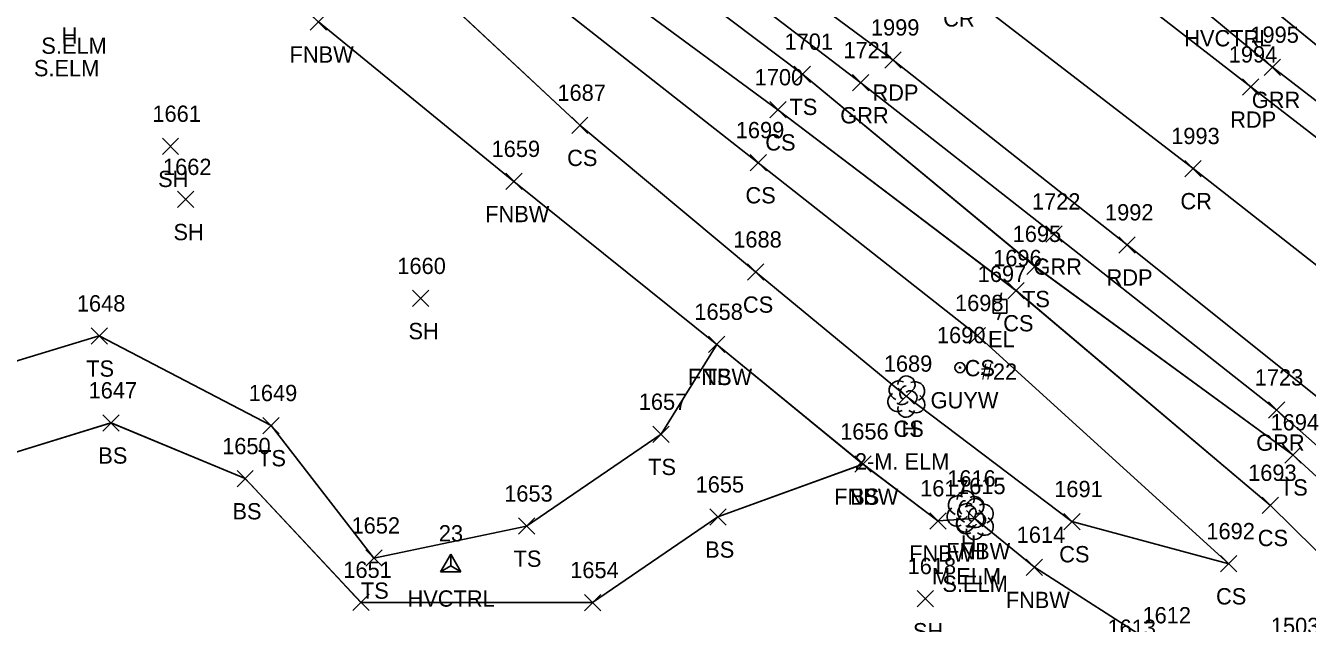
# Model space of a CAD drawing. Extents: x 1415642 to 1422021, y 544543 to 547232.
# Drawn here: x 1415966.4 to 1416123.6, y 546804.9 to 546878.2 of the extents above; entities that cross this region are included whole.
import ezdxf

# ---------------------------------------------------------------- set-up
doc = ezdxf.new("R2010")
doc.units = 0
for name, color, linetype in [('C_A', 7, 'Continuous'), ('C_I', 7, 'Continuous'), ('CPSM', 7, 'Continuous'), ('L_A', 7, 'Continuous'), ('L_C', 7, 'Continuous'), ('L_I', 7, 'Continuous'), ('L_TIC', 7, 'Continuous'), ('LELB', 7, 'Continuous'), ('LFNC', 7, 'Continuous'), ('LTD', 7, 'Continuous'), ('P_A', 7, 'Continuous'), ('P_I', 7, 'Continuous'), ('P_TIC', 7, 'Continuous'), ('PET', 7, 'Continuous'), ('PRC', 7, 'Continuous'), ('R_A', 7, 'Continuous'), ('R_I', 7, 'Continuous'), ('R_TIC', 7, 'Continuous'), ('RGR', 7, 'Continuous'), ('U_A', 7, 'Continuous'), ('U_C', 7, 'Continuous'), ('U_I', 7, 'Continuous'), ('UEPT', 7, 'Continuous'), ('UPGW', 7, 'Continuous')]:
    doc.layers.add(name, color=color, linetype=linetype)

msp = doc.modelspace()

# ---------------------------------------------------------------- linework, layer by layer
at = {"layer": 'CPSM'}
for p, q in [((1416017.27, 546811.23), (1416018.52, 546813.39)), ((1416019.77, 546811.23), (1416018.52, 546813.39)), ((1416018.52, 546811.95), (1416018.52, 546813.39)), ((1416017.27, 546811.23), (1416018.52, 546811.95)), ((1416017.27, 546811.23), (1416019.77, 546811.23)), ((1416018.52, 546811.95), (1416018.52, 546811.95)), ((1416018.52, 546811.95), (1416019.77, 546811.23))]:
    msp.add_line(p, q, dxfattribs=at)
at = {"layer": 'L_TIC'}
for points in [[(1416001.28, 546877.71), (1416003.28, 546879.71)], [(1416003.28, 546877.71), (1416001.28, 546879.71)], [(1416060.67, 546871.28), (1416062.67, 546873.28)], [(1416062.67, 546871.28), (1416060.67, 546873.28)], [(1416057.66, 546866.92), (1416059.66, 546868.92)], [(1416059.66, 546866.92), (1416057.66, 546868.92)], [(1416033.36, 546865.02), (1416035.36, 546867.02)], [(1416035.36, 546865.02), (1416033.36, 546867.02)], [(1415983.14, 546862.44), (1415985.14, 546864.44)], [(1415985.14, 546862.44), (1415983.14, 546864.44)], [(1416055.24, 546860.43), (1416057.24, 546862.43)], [(1416057.24, 546860.43), (1416055.24, 546862.43)], [(1416025.27, 546858.13), (1416027.27, 546860.13)], [(1416027.27, 546858.13), (1416025.27, 546860.13)], [(1415985.01, 546855.92), (1415987.01, 546857.92)], [(1415987.01, 546855.92), (1415985.01, 546857.92)], [(1416054.92, 546847.02), (1416056.92, 546849.02)], [(1416056.92, 546847.02), (1416054.92, 546849.02)], [(1416089.2, 546847.7), (1416091.2, 546849.7)], [(1416091.2, 546847.7), (1416089.2, 546849.7)], [(1416086.86, 546844.73), (1416088.86, 546846.73)], [(1416088.86, 546844.73), (1416086.86, 546846.73)], [(1416013.84, 546843.77), (1416015.84, 546845.77)], [(1416015.84, 546843.77), (1416013.84, 546845.77)], [(1415974.39, 546839.17), (1415976.39, 546841.17)], [(1415976.39, 546839.17), (1415974.39, 546841.17)], [(1416082.13, 546839.22), (1416084.13, 546841.22)], [(1416084.13, 546839.22), (1416082.13, 546841.22)], [(1416050.15, 546838.14), (1416052.15, 546840.14)], [(1416052.15, 546838.14), (1416050.15, 546840.14)], [(1416050.15, 546838.14), (1416052.15, 546840.14)], [(1416052.15, 546838.14), (1416050.15, 546840.14)], [(1416073.4, 546831.78), (1416075.4, 546833.78)], [(1416075.4, 546831.78), (1416073.4, 546833.78)], [(1415975.83, 546828.5), (1415977.83, 546830.5)], [(1415977.83, 546828.5), (1415975.83, 546830.5)], [(1415995.48, 546828.17), (1415997.48, 546830.17)], [(1415997.48, 546828.17), (1415995.48, 546830.17)], [(1416043.33, 546827.1), (1416045.33, 546829.1)], [(1416045.33, 546827.1), (1416043.33, 546829.1)], [(1416120.84, 546824.58), (1416122.84, 546826.58)], [(1416122.84, 546824.58), (1416120.84, 546826.58)], [(1416068.09, 546823.45), (1416070.09, 546825.45)], [(1416070.09, 546823.45), (1416068.09, 546825.45)], [(1416068.09, 546823.45), (1416070.09, 546825.45)], [(1416070.09, 546823.45), (1416068.09, 546825.45)], [(1415992.3, 546821.66), (1415994.3, 546823.66)], [(1415994.3, 546821.66), (1415992.3, 546823.66)], [(1416118.09, 546818.38), (1416120.09, 546820.38)], [(1416120.09, 546818.38), (1416118.09, 546820.38)], [(1416050.3, 546816.96), (1416052.3, 546818.96)], [(1416052.3, 546816.96), (1416050.3, 546818.96)], [(1416077.29, 546816.48), (1416079.29, 546818.48)], [(1416079.29, 546816.48), (1416077.29, 546818.48)], [(1416081.81, 546816.76), (1416083.81, 546818.76)], [(1416083.81, 546816.76), (1416081.81, 546818.76)], [(1416093.73, 546816.39), (1416095.73, 546818.39)], [(1416095.73, 546816.39), (1416093.73, 546818.39)], [(1416026.82, 546815.84), (1416028.82, 546817.84)], [(1416028.82, 546815.84), (1416026.82, 546817.84)], [(1416008.09, 546811.92), (1416010.09, 546813.92)], [(1416010.09, 546811.92), (1416008.09, 546813.92)], [(1416089.13, 546810.78), (1416091.13, 546812.78)], [(1416091.13, 546810.78), (1416089.13, 546812.78)], [(1416112.97, 546811.22), (1416114.97, 546813.22)], [(1416114.97, 546811.22), (1416112.97, 546813.22)], [(1416075.74, 546806.94), (1416077.74, 546808.94)], [(1416077.74, 546806.94), (1416075.74, 546808.94)], [(1416006.51, 546806.48), (1416008.51, 546808.48)], [(1416008.51, 546806.48), (1416006.51, 546808.48)], [(1416034.92, 546806.45), (1416036.92, 546808.45)], [(1416036.92, 546806.45), (1416034.92, 546808.45)]]:
    msp.add_lwpolyline(points, dxfattribs=at)
at = {"layer": 'LELB'}
for points in [[(1416210.45, 546810.14), (1416187.24, 546828.5), (1416172.35, 546839.03), (1416162.91, 546845.64), (1416145.69, 546861.76), (1416125.16, 546875.54), (1416093.4, 546901.43), (1416075.19, 546919.9), (1416045.66, 546942.32), (1416039.77, 546946.29), (1416015.88, 546971.97), (1415979.91, 546993.7), (1415946.5, 547018.2), (1415914.22, 547042.27), (1415877.25, 547066.68), (1415845.5, 547087.74)], [(1416210.45, 546810.14), (1416187.24, 546828.5), (1416172.36, 546839.03), (1416162.91, 546845.64), (1416145.7, 546861.76), (1416125.16, 546875.54), (1416093.4, 546901.44), (1416075.18, 546919.9), (1416045.66, 546942.32), (1416039.77, 546946.29), (1416015.88, 546971.97), (1415979.91, 546993.7), (1415946.51, 547018.2), (1415914.22, 547042.27), (1415877.24, 547066.68), (1415845.5, 547087.74)], [(1416200.69, 546756.25), (1416177.76, 546767.63), (1416166.72, 546775.57), (1416158.94, 546780.74), (1416149.8, 546790.95), (1416145.27, 546792.19), (1416135.47, 546803.24), (1416119.09, 546819.38), (1416087.86, 546845.73), (1416058.66, 546867.92), (1416017.63, 546898.15), (1415975.94, 546926.54), (1415961.59, 546937.35), (1415930.25, 546967.22), (1415904.85, 546987.6), (1415883.27, 547005.7), (1415850.56, 547030.99), (1415821.69, 547055.02)], [(1416200.69, 546756.25), (1416177.77, 546767.63), (1416166.72, 546775.57), (1416158.93, 546780.74), (1416149.8, 546790.95), (1416145.28, 546792.19), (1416135.47, 546803.24), (1416119.09, 546819.38), (1416087.87, 546845.73), (1416058.67, 546867.92), (1416017.63, 546898.16), (1415975.95, 546926.55), (1415961.6, 546937.34), (1415930.25, 546967.22), (1415904.86, 546987.6), (1415883.28, 547005.7), (1415850.57, 547030.99), (1415821.7, 547055.02)], [(1415881.61, 546996.31), (1415913.06, 546969.47), (1415944.07, 546943.36), (1415978.11, 546916.22), (1416009.92, 546888.85), (1416034.36, 546866.02), (1416055.92, 546848.02), (1416074.4, 546832.78), (1416094.73, 546817.39), (1416113.97, 546812.22), (1416083.13, 546840.22), (1416056.24, 546861.43), (1416014.25, 546894.44), (1415975.94, 546926.54)], [(1415881.62, 546996.31), (1415913.07, 546969.47), (1415944.08, 546943.36), (1415978.12, 546916.23), (1416009.93, 546888.84), (1416034.36, 546866.03), (1416055.93, 546848.02), (1416074.4, 546832.78), (1416094.74, 546817.39), (1416113.98, 546812.22), (1416083.14, 546840.22), (1416056.24, 546861.43), (1416014.25, 546894.43), (1415975.95, 546926.55)], [(1416413.88, 546519.84), (1416385.73, 546558.12), (1416356.85, 546595.36), (1416336.82, 546621.39), (1416300.66, 546661.66), (1416278.22, 546684.25), (1416249.88, 546714.04), (1416230.93, 546728.9), (1416221.86, 546737.5), (1416200.69, 546756.25), (1416176.24, 546778.44), (1416157.26, 546793.38), (1416140.02, 546808.9), (1416121.84, 546825.58), (1416090.2, 546848.7), (1416061.67, 546872.28), (1416021.03, 546902.96), (1415979.27, 546932.57), (1415964.6, 546940.59)], [(1416413.88, 546519.84), (1416385.73, 546558.12), (1416356.85, 546595.36), (1416336.82, 546621.39), (1416300.66, 546661.66), (1416278.22, 546684.25), (1416249.88, 546714.04), (1416230.93, 546728.9), (1416221.87, 546737.51), (1416200.69, 546756.25), (1416176.24, 546778.44), (1416157.26, 546793.38), (1416140.03, 546808.9), (1416121.84, 546825.58), (1416090.21, 546848.7), (1416061.68, 546872.28), (1416021.04, 546902.96), (1415979.28, 546932.57), (1415964.61, 546940.59)], [(1415936.18, 546816.47), (1415954.66, 546833.88), (1415975.39, 546840.17), (1415996.48, 546829.17), (1416009.09, 546812.92), (1416027.82, 546816.84), (1416044.33, 546828.1), (1416051.15, 546839.14)], [(1415936.19, 546816.47), (1415954.66, 546833.88), (1415975.4, 546840.17), (1415996.49, 546829.17), (1416009.1, 546812.92), (1416027.83, 546816.84), (1416044.34, 546828.1), (1416051.16, 546839.14)], [(1415944.33, 546804.96), (1415961.56, 546824.81), (1415976.83, 546829.5), (1415993.3, 546822.66), (1416007.51, 546807.48), (1416035.92, 546807.45), (1416051.3, 546817.96), (1416069.09, 546824.45)], [(1415944.33, 546804.96), (1415961.57, 546824.81), (1415976.84, 546829.5), (1415993.31, 546822.66), (1416007.52, 546807.48), (1416035.92, 546807.45), (1416051.3, 546817.96), (1416069.1, 546824.45)]]:
    msp.add_lwpolyline(points, dxfattribs=at)
at = {"layer": 'LFNC'}
for points in [[(1416115.75, 546796.75), (1416105.56, 546801.9), (1416090.13, 546811.78), (1416082.81, 546817.76), (1416078.29, 546817.48), (1416069.09, 546824.45), (1416051.15, 546839.14), (1416026.27, 546859.13), (1416002.28, 546878.71), (1415967.43, 546909.62), (1415937.82, 546934.52), (1415909.35, 546961.09), (1415874.55, 546995.04)], [(1416115.75, 546796.75), (1416105.57, 546801.9), (1416090.14, 546811.78), (1416082.82, 546817.76), (1416078.29, 546817.48), (1416069.1, 546824.45), (1416051.16, 546839.14), (1416026.28, 546859.13), (1416002.28, 546878.71), (1415967.43, 546909.62), (1415937.83, 546934.51), (1415909.36, 546961.09), (1415874.56, 546995.04)]]:
    msp.add_lwpolyline(points, dxfattribs=at)
at = {"layer": 'LTD'}
for p, q in [((1416074.4, 546832.78), (1416074.4, 546832.78)), ((1416074.4, 546832.78), (1416074.4, 546832.78)), ((1416081.65, 546818.69), (1416081.65, 546818.69)), ((1416081.65, 546818.69), (1416081.65, 546818.69)), ((1416082.81, 546817.76), (1416082.81, 546817.76)), ((1416082.81, 546817.76), (1416082.81, 546817.76))]:
    msp.add_line(p, q, dxfattribs=at)
for centre in [(1416074.44, 546834.21), (1416081.7, 546820.13), (1416082.86, 546819.19)]:
    msp.add_arc(centre, 1.05, 335.5272, 180.9563, dxfattribs=at)
for centre, major_axis, ratio, start_param, end_param in [((1416073.6, 546833.45), (1.21, -0.51), 0.895232, 1.570796, 4.712389), ((1416074.19, 546833.24), (-0.208, -0.792), 0.645439, 3.141593, 6.283185), ((1416075.44, 546833.36), (-1.14, -0.48), 0.949671, 1.570796, 4.712389), ((1416073.31, 546832.07), (0.58, -1.04), 0.959034, 3.141593, 6.283185), ((1416074.9, 546832.61), (-0.5, 0.667), 0.989748, 3.141593, 6.283185), ((1416075.4, 546831.95), (-1.09, 0.79), 0.841452, 1.570796, 4.712389), ((1416074.4, 546831.28), (0.26, 1.06), 0.942809, 1.570796, 4.712389), ((1416073.94, 546832.03), (-0.625, -0.083), 0.423636, 0, 3.141593), ((1416080.86, 546819.36), (1.21, -0.51), 0.895232, 1.570796, 4.712389), ((1416081.45, 546819.15), (-0.208, -0.792), 0.645439, 3.141593, 6.283185), ((1416082.7, 546819.28), (-1.14, -0.48), 0.949671, 1.570796, 4.712389), ((1416080.57, 546817.99), (0.58, -1.04), 0.959034, 3.141593, 6.283185), ((1416082.02, 546818.42), (1.21, -0.51), 0.895232, 1.570796, 4.712389), ((1416082.15, 546818.53), (-0.5, 0.667), 0.989748, 3.141593, 6.283185), ((1416082.6, 546818.22), (-0.208, -0.792), 0.645439, 3.141593, 6.283185), ((1416082.66, 546817.86), (-1.09, 0.79), 0.841452, 1.570796, 4.712389), ((1416083.31, 546817.59), (-0.5, 0.667), 0.989748, 3.141593, 6.283185), ((1416083.85, 546818.34), (-1.14, -0.48), 0.949671, 1.570796, 4.712389), ((1416081.73, 546817.05), (0.58, -1.04), 0.959034, 3.141593, 6.283185), ((1416081.66, 546817.19), (0.26, 1.06), 0.942809, 1.570796, 4.712389), ((1416081.2, 546817.94), (-0.625, -0.083), 0.423636, 0, 3.141593), ((1416082.35, 546817.01), (-0.625, -0.083), 0.423636, 0, 3.141593), ((1416083.81, 546816.92), (-1.09, 0.79), 0.841452, 1.570796, 4.712389), ((1416082.81, 546816.26), (0.26, 1.06), 0.942809, 1.570796, 4.712389)]:
    msp.add_ellipse(centre, major_axis=major_axis, ratio=ratio, start_param=start_param, end_param=end_param, dxfattribs=at)
at = {"layer": 'P_TIC'}
for points in [[(1416071.78, 546873.03), (1416073.78, 546875.03)], [(1416073.78, 546873.03), (1416071.78, 546875.03)], [(1416115.66, 546869.72), (1416117.66, 546871.72)], [(1416117.66, 546869.72), (1416115.66, 546871.72)], [(1416108.6, 546859.71), (1416110.6, 546861.71)], [(1416110.6, 546859.71), (1416108.6, 546861.71)], [(1416100.49, 546850.34), (1416102.49, 546852.34)], [(1416102.49, 546850.34), (1416100.49, 546852.34)]]:
    msp.add_lwpolyline(points, dxfattribs=at)
at = {"layer": 'PET'}
for points in [[(1416435.56, 546537.44), (1416408.53, 546574.61), (1416379.54, 546611.97), (1416358.62, 546637.86), (1416320.38, 546681.18), (1416299.04, 546704.62), (1416270.68, 546734.26), (1416256.1, 546749.21), (1416221.42, 546781.44), (1416197.8, 546803.68), (1416167.45, 546829.93), (1416146.9, 546847.39), (1416116.66, 546870.72), (1416088.42, 546892.72), (1416062.97, 546911.59), (1416031.6, 546935.61), (1415998.08, 546959.73), (1415969.06, 546981.93), (1415936.64, 547006.92)], [(1416435.56, 546537.44), (1416408.53, 546574.62), (1416379.54, 546611.97), (1416358.63, 546637.85), (1416320.38, 546681.18), (1416299.04, 546704.62), (1416270.69, 546734.26), (1416256.1, 546749.21), (1416221.42, 546781.44), (1416197.8, 546803.68), (1416167.45, 546829.93), (1416146.9, 546847.38), (1416116.66, 546870.72), (1416088.42, 546892.72), (1416062.98, 546911.58), (1416031.6, 546935.61), (1415998.08, 546959.73), (1415969.07, 546981.93), (1415936.65, 547006.92)], [(1416417.68, 546520.98), (1416388.9, 546560.28), (1416359.4, 546597.75), (1416339.06, 546622.92), (1416303.08, 546664.45), (1416282.37, 546687.64), (1416253.58, 546717.16), (1416237.44, 546733.28), (1416206.51, 546762.17), (1416181.86, 546784.67), (1416151.94, 546810.47), (1416130.39, 546828.26), (1416101.49, 546851.34), (1416072.78, 546874.03), (1416047.41, 546892.82), (1416017.81, 546915.59), (1415982.21, 546942.39), (1415954.4, 546964.56)], [(1416417.68, 546520.98), (1416388.9, 546560.28), (1416359.4, 546597.76), (1416339.06, 546622.93), (1416303.08, 546664.45), (1416282.37, 546687.65), (1416253.58, 546717.16), (1416237.44, 546733.28), (1416206.51, 546762.17), (1416181.87, 546784.67), (1416151.94, 546810.47), (1416130.39, 546828.26), (1416101.49, 546851.34), (1416072.78, 546874.03), (1416047.41, 546892.82), (1416017.81, 546915.59), (1415982.21, 546942.39), (1415954.4, 546964.56)]]:
    msp.add_lwpolyline(points, dxfattribs=at)
at = {"layer": 'PRC'}
for points in [[(1416425.29, 546532.23), (1416399.16, 546568.17), (1416370.34, 546605), (1416349.98, 546630.03), (1416312.55, 546673.44), (1416291.21, 546696.63), (1416262.58, 546725.99), (1416246.66, 546742.06), (1416214.68, 546772.43), (1416190.4, 546794.67), (1416160.38, 546819.82), (1416139.01, 546837.64), (1416109.6, 546860.71), (1416080.51, 546883.13), (1416051.44, 546902.01), (1416024.84, 546926.07), (1415989.92, 546951.67), (1415962.46, 546973.18)], [(1416425.29, 546532.24), (1416399.16, 546568.17), (1416370.35, 546605), (1416349.98, 546630.03), (1416312.55, 546673.45), (1416291.21, 546696.63), (1416262.58, 546725.99), (1416246.66, 546742.06), (1416214.67, 546772.43), (1416190.4, 546794.67), (1416160.38, 546819.82), (1416139.01, 546837.64), (1416109.6, 546860.71), (1416080.51, 546883.13), (1416051.45, 546902.01), (1416024.84, 546926.07), (1415989.92, 546951.68), (1415962.46, 546973.18)]]:
    msp.add_lwpolyline(points, dxfattribs=at)
at = {"layer": 'R_TIC'}
for points in [[(1416118.32, 546872.14), (1416120.32, 546874.14)], [(1416120.32, 546872.14), (1416118.32, 546874.14)], [(1416067.82, 546870.25), (1416069.82, 546872.25)], [(1416069.82, 546870.25), (1416067.82, 546872.25)], [(1416091.52, 546851.68), (1416093.52, 546853.68)], [(1416093.52, 546851.68), (1416091.52, 546853.68)], [(1416118.85, 546830.08), (1416120.85, 546832.08)], [(1416120.85, 546830.08), (1416118.85, 546832.08)]]:
    msp.add_lwpolyline(points, dxfattribs=at)
at = {"layer": 'RGR'}
for points in [[(1415969.74, 546941.99), (1415991.65, 546929.21), (1416016.29, 546910.93), (1416041.47, 546892.17), (1416068.82, 546871.25), (1416092.52, 546852.68), (1416119.85, 546831.08), (1416143.05, 546810.55), (1416160.13, 546797.47)], [(1415969.75, 546941.99), (1415991.65, 546929.21), (1416016.3, 546910.93), (1416041.48, 546892.18), (1416068.83, 546871.25), (1416092.52, 546852.68), (1416119.86, 546831.08), (1416143.05, 546810.55), (1416160.13, 546797.47)], [(1416226.79, 546787.66), (1416201.13, 546806.07), (1416168.8, 546834.69), (1416149.29, 546850.1), (1416119.32, 546873.14), (1416091.47, 546896.23), (1416072.68, 546914.46)], [(1416226.79, 546787.66), (1416201.13, 546806.07), (1416168.81, 546834.68), (1416149.29, 546850.1), (1416119.32, 546873.14), (1416091.47, 546896.23), (1416072.68, 546914.46)]]:
    msp.add_lwpolyline(points, dxfattribs=at)
at = {"layer": 'UEPT'}
for p, q in [((1416086.08, 546845.46), (1416085.91, 546844.63)), ((1416085.08, 546842.96), (1416085.08, 546844.63)), ((1416085.08, 546844.63), (1416086.74, 546844.63)), ((1416085.91, 546843.79), (1416085.91, 546843.79)), ((1416086.74, 546844.63), (1416086.74, 546842.96)), ((1416086.74, 546842.96), (1416085.08, 546842.96)), ((1416085.66, 546842.13), (1416085.91, 546842.96))]:
    msp.add_line(p, q, dxfattribs=at)
at = {"layer": 'UPGW'}
for radius in [0.625, 0.0833]:
    msp.add_circle((1416081, 546836.28), radius, dxfattribs=at)

# ---------------------------------------------------------------- texts
at = {"layer": 'C_A'}
for p in [(1416108.51, 546875.7), (1416013.22, 546806.95)]:
    msp.add_text('HVCTRL', height=2, dxfattribs=at).set_placement(p)
at = {"layer": 'C_I'}
msp.add_text('23', height=2, dxfattribs=at).set_placement((1416017.06, 546814.95))
at = {"layer": 'L_A'}
for s, p in [('H', (1415970.78, 546876.03)), ('FNBW', (1415998.75, 546873.71)), ('TS', (1416060.08, 546867.28)), ('CS', (1416057.11, 546862.92)), ('CS', (1416032.8, 546861.02)), ('SH', (1415982.62, 546858.44)), ('CS', (1416054.68, 546856.43)), ('FNBW', (1416022.75, 546854.13)), ('SH', (1415984.5, 546851.92)), ('TS', (1416088.61, 546843.7)), ('CS', (1416054.37, 546843.02)), ('CS', (1416086.3, 546840.73)), ('SH', (1416013.33, 546839.77)), ('CS', (1416081.57, 546835.22)), ('TS', (1415973.8, 546835.17)), ('FNBW', (1416047.62, 546834.14)), ('TS', (1416049.56, 546834.14)), ('CS', (1416072.84, 546827.78)), ('H', (1416073.83, 546827.78)), ('BS', (1415975.28, 546824.5)), ('TS', (1415994.89, 546824.17)), ('TS', (1416042.74, 546823.1)), ('BS', (1416067.53, 546819.45)), ('TS', (1416120.25, 546820.58)), ('FNBW', (1416065.57, 546819.45)), ('BS', (1415991.74, 546817.66)), ('H', (1416081.09, 546813.69)), ('CS', (1416117.53, 546814.38)), ('TS', (1416026.23, 546811.84)), ('BS', (1416049.74, 546812.96)), ('FNBW', (1416074.76, 546812.48)), ('FNBW', (1416079.29, 546812.76)), ('H', (1416082.25, 546812.76)), ('CS', (1416093.17, 546812.39)), ('TS', (1416007.5, 546807.92)), ('CS', (1416112.41, 546807.22)), ('FNBW', (1416086.61, 546806.78)), ('SH', (1416075.23, 546802.94))]:
    msp.add_text(s, height=2, dxfattribs=at).set_placement(p)
at = {"layer": 'L_C'}
for s, p in [('S.ELM', (1415968.29, 546874.79)), ('S.ELM', (1415967.38, 546872.03)), ('2-M. ELM', (1416068.1, 546823.78)), ('M.ELM', (1416077.56, 546809.69)), ('S.ELM', (1416078.84, 546808.76))]:
    msp.add_text(s, height=2, dxfattribs=at).set_placement(p)
at = {"layer": 'L_I'}
for s, p in [('1701', (1416059.47, 546875.28)), ('1700', (1416055.81, 546870.92)), ('1687', (1416031.61, 546869.02)), ('1661', (1415981.92, 546866.44)), ('1699', (1416053.49, 546864.43)), ('1659', (1416023.53, 546862.13)), ('1662', (1415983.22, 546859.92)), ('1688', (1416053.18, 546851.02)), ('1695', (1416087.46, 546851.7)), ('1660', (1416011.97, 546847.77)), ('1696', (1416085.07, 546848.73)), ('1648', (1415972.65, 546843.17)), ('1698', (1416080.39, 546843.22)), ('1658', (1416048.41, 546842.14)), ('1658', (1416048.41, 546842.14)), ('1689', (1416071.65, 546835.78)), ('1689', (1416071.65, 546835.78)), ('1647', (1415974.09, 546832.5)), ('1649', (1415993.74, 546832.17)), ('1657', (1416041.59, 546831.1)), ('1656', (1416066.3, 546827.45)), ('1656', (1416066.3, 546827.45)), ('1694', (1416119.1, 546828.58)), ('1650', (1415990.48, 546825.66)), ('1616', (1416079.43, 546821.69)), ('1693', (1416116.35, 546822.38)), ('1653', (1416025.08, 546819.84)), ('1655', (1416048.56, 546820.96)), ('1617', (1416076.11, 546820.48)), ('1615', (1416080.64, 546820.76)), ('1615', (1416080.64, 546820.76)), ('1691', (1416092.56, 546820.39)), ('1652', (1416006.35, 546815.92)), ('1614', (1416087.96, 546814.78)), ('1692', (1416111.23, 546815.22)), ('1651', (1416005.34, 546810.48)), ('1654', (1416033.18, 546810.45)), ('1618', (1416074.57, 546810.94)), ('1612', (1416103.39, 546804.9)), ('1613', (1416099.09, 546803.37)), ('1613', (1416099.09, 546803.37)), ('1503', (1416119.14, 546803.59))]:
    msp.add_text(s, height=2, dxfattribs=at).set_placement(p)
at = {"layer": 'P_A'}
for s, p in [('CR', (1416078.94, 546878.13)), ('RDP', (1416070.26, 546869.03)), ('RDP', (1416114.15, 546865.72)), ('CR', (1416108.04, 546855.71)), ('RDP', (1416098.98, 546846.34))]:
    msp.add_text(s, height=2, dxfattribs=at).set_placement(p)
at = {"layer": 'P_I'}
for s, p in [('1999', (1416070.07, 546877.03)), ('1994', (1416113.97, 546873.72)), ('1993', (1416106.91, 546863.71)), ('1992', (1416098.79, 546854.34))]:
    msp.add_text(s, height=2, dxfattribs=at).set_placement(p)
at = {"layer": 'R_A'}
for p in [(1416116.8, 546868.14), (1416066.31, 546866.25), (1416090.01, 546847.68), (1416117.34, 546826.08)]:
    msp.add_text('GRR', height=2, dxfattribs=at).set_placement(p)
at = {"layer": 'R_I'}
for s, p in [('1995', (1416116.62, 546876.14)), ('1721', (1416066.7, 546874.25)), ('1722', (1416089.83, 546855.68)), ('1723', (1416117.16, 546834.08))]:
    msp.add_text(s, height=2, dxfattribs=at).set_placement(p)
at = {"layer": 'U_A'}
for s, p in [('EL', (1416084.44, 546838.79)), ('GUYW', (1416077.39, 546831.28))]:
    msp.add_text(s, height=2, dxfattribs=at).set_placement(p)
at = {"layer": 'U_C'}
msp.add_text('#22', height=2, dxfattribs=at).set_placement((1416083.55, 546834.79))
at = {"layer": 'U_I'}
for s, p in [('1697', (1416083.17, 546846.79)), ('1690', (1416078.17, 546839.28))]:
    msp.add_text(s, height=2, dxfattribs=at).set_placement(p)

doc.saveas('drawing.dxf')
